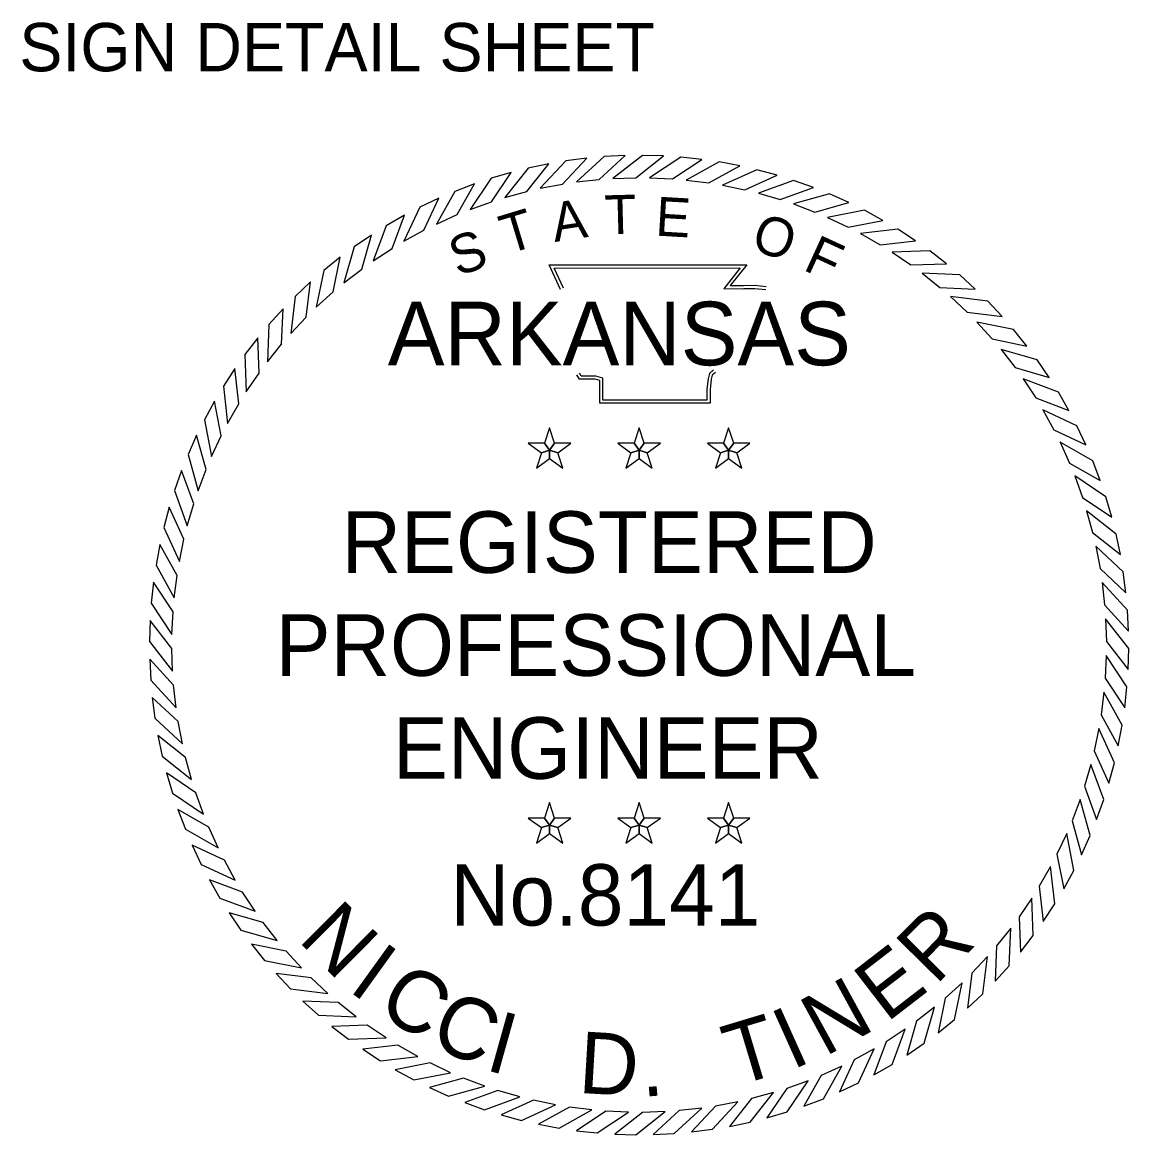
# Model space of a CAD drawing. Extents: x 1001970.7 to 1001981.7, y 1841148.9 to 1841208.3.
import ezdxf

# ---------------------------------------------------------------- set-up
doc = ezdxf.new("R2010")
doc.units = 0
doc.layers.add('G-ANNO-SYMB', color=7, linetype='Continuous')
doc.layers.add('G-ANNO-TEXT', color=7, linetype='Continuous')

msp = doc.modelspace()

# ---------------------------------------------------------------- linework, layer by layer
at = {"layer": 'G-ANNO-SYMB'}
for points in [[(1001977.6873, 1841207.3349), (1001977.5317, 1841207.3147), (1001977.3411, 1841207.1103), (1001977.5075, 1841207.1421)], [(1001977.973, 1841207.3543), (1001977.8164, 1841207.3464), (1001977.6103, 1841207.1575), (1001977.7787, 1841207.1762)], [(1001978.2594, 1841207.3512), (1001978.1026, 1841207.3557), (1001977.8823, 1841207.1836), (1001978.0517, 1841207.1889)], [(1001978.5447, 1841207.3257), (1001978.3887, 1841207.3424), (1001978.1556, 1841207.1881), (1001978.3249, 1841207.1802)], [(1001977.404, 1841207.2931), (1001977.2505, 1841207.2608), (1001977.0764, 1841207.042), (1001977.2399, 1841207.0868)], [(1001978.8271, 1841207.2779), (1001978.6729, 1841207.3068), (1001978.4284, 1841207.1713), (1001978.5965, 1841207.1501)], [(1001979.1048, 1841207.208), (1001978.9534, 1841207.249), (1001978.699, 1841207.133), (1001978.865, 1841207.0987)], [(1001977.1248, 1841207.2292), (1001976.9743, 1841207.185), (1001976.8179, 1841206.9532), (1001976.9774, 1841207.0107)], [(1001979.3763, 1841207.1166), (1001979.2285, 1841207.1693), (1001978.9658, 1841207.0737), (1001979.1286, 1841207.0265)], [(1001976.8515, 1841207.1436), (1001976.7049, 1841207.0877), (1001976.5672, 1841206.8444), (1001976.7217, 1841206.9142)], [(1001979.6397, 1841207.0042), (1001979.4965, 1841207.0683), (1001979.2271, 1841206.9936), (1001979.3857, 1841206.9338)], [(1001976.5857, 1841207.0368), (1001976.444, 1841206.9696), (1001976.3258, 1841206.7163), (1001976.4743, 1841206.7979)], [(1001976.3291, 1841206.9095), (1001976.1931, 1841206.8314), (1001976.0952, 1841206.5696), (1001976.2368, 1841206.6626)], [(1001979.8935, 1841206.8715), (1001979.7558, 1841206.9466), (1001979.4813, 1841206.8933), (1001979.6347, 1841206.8212)], [(1001976.0834, 1841206.7625), (1001975.9539, 1841206.674), (1001975.8768, 1841206.4052), (1001976.0107, 1841206.5091)], [(1001980.136, 1841206.7192), (1001980.0047, 1841206.8049), (1001979.7269, 1841206.7733), (1001979.8741, 1841206.6894)], [(1001975.8499, 1841206.5967), (1001975.7278, 1841206.4982), (1001975.672, 1841206.2243), (1001975.7973, 1841206.3384)], [(1001980.3659, 1841206.5484), (1001980.2417, 1841206.6442), (1001979.9623, 1841206.6344), (1001980.1025, 1841206.5392)], [(1001975.6301, 1841206.413), (1001975.5161, 1841206.3053), (1001975.482, 1841206.0278), (1001975.598, 1841206.1514)], [(1001980.5817, 1841206.3601), (1001980.4654, 1841206.4653), (1001980.1861, 1841206.4775), (1001980.3184, 1841206.3716)], [(1001980.7821, 1841206.1554), (1001980.6743, 1841206.2694), (1001980.3969, 1841206.3035), (1001980.5204, 1841206.1875)], [(1001975.4254, 1841206.2127), (1001975.3202, 1841206.0963), (1001975.308, 1841205.817), (1001975.4139, 1841205.9493)], [(1001980.9657, 1841205.9357), (1001980.8673, 1841206.0578), (1001980.5933, 1841206.1135), (1001980.7074, 1841205.9882)], [(1001975.2371, 1841205.9969), (1001975.1414, 1841205.8727), (1001975.1511, 1841205.5933), (1001975.2463, 1841205.7334)], [(1001981.1316, 1841205.7022), (1001981.043, 1841205.8316), (1001980.7743, 1841205.9087), (1001980.8782, 1841205.7748)], [(1001975.0663, 1841205.767), (1001974.9806, 1841205.6356), (1001975.0122, 1841205.3579), (1001975.0962, 1841205.5051)], [(1001981.2786, 1841205.4564), (1001981.2005, 1841205.5924), (1001980.9386, 1841205.6903), (1001981.0317, 1841205.5487)], [(1001974.9141, 1841205.5244), (1001974.8389, 1841205.3867), (1001974.8923, 1841205.1123), (1001974.9644, 1841205.2656)], [(1001981.4059, 1841205.1998), (1001981.3387, 1841205.3416), (1001981.0853, 1841205.4597), (1001981.167, 1841205.3112)], [(1001977.4103, 1841205.1607), (1001977.4478, 1841205.2122), (1001977.4103, 1841205.3274), (1001977.3729, 1841205.2122)], [(1001978.0773, 1841205.1607), (1001978.1147, 1841205.2122), (1001978.0773, 1841205.3274), (1001978.0399, 1841205.2122)], [(1001978.7443, 1841205.1607), (1001978.7817, 1841205.2122), (1001978.7443, 1841205.3274), (1001978.7068, 1841205.2122)], [(1001974.7813, 1841205.2706), (1001974.7172, 1841205.1275), (1001974.7919, 1841204.8581), (1001974.8518, 1841205.0166)], [(1001977.4103, 1841205.1607), (1001977.3729, 1841205.2122), (1001977.2517, 1841205.2122), (1001977.3497, 1841205.141)], [(1001977.4103, 1841205.1607), (1001977.3497, 1841205.141), (1001977.3123, 1841205.0258), (1001977.4103, 1841205.097)], [(1001977.4103, 1841205.1607), (1001977.4709, 1841205.141), (1001977.5689, 1841205.2122), (1001977.4478, 1841205.2122)], [(1001977.4103, 1841205.1607), (1001977.4103, 1841205.097), (1001977.5083, 1841205.0258), (1001977.4709, 1841205.141)], [(1001978.0773, 1841205.1607), (1001978.0399, 1841205.2122), (1001977.9187, 1841205.2122), (1001978.0167, 1841205.141)], [(1001978.0773, 1841205.1607), (1001978.0167, 1841205.141), (1001977.9793, 1841205.0258), (1001978.0773, 1841205.097)], [(1001978.0773, 1841205.1607), (1001978.1379, 1841205.141), (1001978.2359, 1841205.2122), (1001978.1147, 1841205.2122)], [(1001978.0773, 1841205.1607), (1001978.0773, 1841205.097), (1001978.1753, 1841205.0258), (1001978.1379, 1841205.141)], [(1001978.7443, 1841205.1607), (1001978.7068, 1841205.2122), (1001978.5857, 1841205.2122), (1001978.6837, 1841205.141)], [(1001978.7443, 1841205.1607), (1001978.6837, 1841205.141), (1001978.6463, 1841205.0258), (1001978.7443, 1841205.097)], [(1001978.7443, 1841205.1607), (1001978.8048, 1841205.141), (1001978.9029, 1841205.2122), (1001978.7817, 1841205.2122)], [(1001978.7443, 1841205.1607), (1001978.7443, 1841205.097), (1001978.8423, 1841205.0258), (1001978.8048, 1841205.141)], [(1001981.5127, 1841204.9341), (1001981.4568, 1841205.0806), (1001981.2135, 1841205.2183), (1001981.2832, 1841205.0639)], [(1001974.6689, 1841205.0072), (1001974.6162, 1841204.8595), (1001974.7118, 1841204.5968), (1001974.7591, 1841204.7595)], [(1001981.5982, 1841204.6608), (1001981.554, 1841204.8113), (1001981.3223, 1841204.9676), (1001981.3797, 1841204.8082)], [(1001974.5775, 1841204.7358), (1001974.5366, 1841204.5844), (1001974.6525, 1841204.33), (1001974.6868, 1841204.4959)], [(1001981.6621, 1841204.3816), (1001981.6299, 1841204.5351), (1001981.4111, 1841204.7091), (1001981.4558, 1841204.5457)], [(1001974.5077, 1841204.458), (1001974.4787, 1841204.3039), (1001974.6143, 1841204.0593), (1001974.6355, 1841204.2275)], [(1001981.7039, 1841204.0982), (1001981.6838, 1841204.2538), (1001981.4793, 1841204.4445), (1001981.5111, 1841204.278)], [(1001974.4598, 1841204.1756), (1001974.4431, 1841204.0197), (1001974.5974, 1841203.7866), (1001974.6053, 1841203.9558)], [(1001981.7233, 1841203.8125), (1001981.7155, 1841203.9691), (1001981.5266, 1841204.1753), (1001981.5452, 1841204.0068)], [(1001974.4343, 1841203.8904), (1001974.4299, 1841203.7336), (1001974.602, 1841203.5133), (1001974.5966, 1841203.6827)], [(1001981.7203, 1841203.5261), (1001981.7247, 1841203.6829), (1001981.5526, 1841203.9032), (1001981.558, 1841203.7338)], [(1001974.4313, 1841203.604), (1001974.4391, 1841203.4473), (1001974.628, 1841203.2412), (1001974.6093, 1841203.4096)], [(1001981.6947, 1841203.2408), (1001981.7115, 1841203.3968), (1001981.5572, 1841203.6299), (1001981.5493, 1841203.4607)], [(1001981.6469, 1841202.9585), (1001981.6759, 1841203.1126), (1001981.5403, 1841203.3571), (1001981.5191, 1841203.189)], [(1001974.4507, 1841203.3183), (1001974.4708, 1841203.1627), (1001974.6753, 1841202.972), (1001974.6435, 1841203.1385)], [(1001974.4925, 1841203.0349), (1001974.5247, 1841202.8814), (1001974.7435, 1841202.7074), (1001974.6988, 1841202.8708)], [(1001981.5771, 1841202.6807), (1001981.618, 1841202.8321), (1001981.5021, 1841203.0865), (1001981.4678, 1841202.9206)], [(1001974.5563, 1841202.7557), (1001974.6005, 1841202.6052), (1001974.8323, 1841202.4489), (1001974.7749, 1841202.6083)], [(1001981.4857, 1841202.4093), (1001981.5384, 1841202.557), (1001981.4428, 1841202.8197), (1001981.3955, 1841202.657)], [(1001977.4103, 1841202.3677), (1001977.4478, 1841202.4193), (1001977.4103, 1841202.5345), (1001977.3729, 1841202.4193)], [(1001978.0773, 1841202.3677), (1001978.1147, 1841202.4193), (1001978.0773, 1841202.5345), (1001978.0399, 1841202.4193)], [(1001978.7443, 1841202.3677), (1001978.7817, 1841202.4193), (1001978.7443, 1841202.5345), (1001978.7068, 1841202.4193)], [(1001981.3733, 1841202.1459), (1001981.4374, 1841202.289), (1001981.3627, 1841202.5584), (1001981.3028, 1841202.3999)], [(1001974.6419, 1841202.4824), (1001974.6978, 1841202.3358), (1001974.9411, 1841202.1982), (1001974.8714, 1841202.3526)], [(1001977.4103, 1841202.3677), (1001977.3729, 1841202.4193), (1001977.2517, 1841202.4193), (1001977.3497, 1841202.3481)], [(1001977.4103, 1841202.3677), (1001977.3497, 1841202.3481), (1001977.3123, 1841202.2328), (1001977.4103, 1841202.304)], [(1001977.4103, 1841202.3677), (1001977.4709, 1841202.3481), (1001977.5689, 1841202.4193), (1001977.4478, 1841202.4193)], [(1001977.4103, 1841202.3677), (1001977.4103, 1841202.304), (1001977.5083, 1841202.2328), (1001977.4709, 1841202.3481)], [(1001978.0773, 1841202.3677), (1001978.0399, 1841202.4193), (1001977.9187, 1841202.4193), (1001978.0167, 1841202.3481)], [(1001978.0773, 1841202.3677), (1001978.0167, 1841202.3481), (1001977.9793, 1841202.2328), (1001978.0773, 1841202.304)], [(1001978.0773, 1841202.3677), (1001978.1379, 1841202.3481), (1001978.2359, 1841202.4193), (1001978.1147, 1841202.4193)], [(1001978.0773, 1841202.3677), (1001978.0773, 1841202.304), (1001978.1753, 1841202.2328), (1001978.1379, 1841202.3481)], [(1001978.7443, 1841202.3677), (1001978.7068, 1841202.4193), (1001978.5857, 1841202.4193), (1001978.6837, 1841202.3481)], [(1001978.7443, 1841202.3677), (1001978.6837, 1841202.3481), (1001978.6463, 1841202.2328), (1001978.7443, 1841202.304)], [(1001978.7443, 1841202.3677), (1001978.8048, 1841202.3481), (1001978.9029, 1841202.4193), (1001978.7817, 1841202.4193)], [(1001978.7443, 1841202.3677), (1001978.7443, 1841202.304), (1001978.8423, 1841202.2328), (1001978.8048, 1841202.3481)], [(1001981.2405, 1841201.8921), (1001981.3157, 1841202.0298), (1001981.2623, 1841202.3042), (1001981.1902, 1841202.1508)], [(1001974.7487, 1841202.2167), (1001974.8159, 1841202.0749), (1001975.0693, 1841201.9568), (1001974.9876, 1841202.1053)], [(1001981.0883, 1841201.6495), (1001981.174, 1841201.7809), (1001981.1423, 1841202.0586), (1001981.0584, 1841201.9114)], [(1001974.876, 1841201.9601), (1001974.9541, 1841201.8241), (1001975.216, 1841201.7262), (1001975.1229, 1841201.8678)], [(1001980.9175, 1841201.4196), (1001981.0132, 1841201.5438), (1001981.0035, 1841201.8232), (1001980.9083, 1841201.683)], [(1001975.023, 1841201.7143), (1001975.1116, 1841201.5848), (1001975.3803, 1841201.5078), (1001975.2764, 1841201.6417)], [(1001980.7291, 1841201.2038), (1001980.8344, 1841201.3202), (1001980.8466, 1841201.5995), (1001980.7406, 1841201.4672)], [(1001975.1889, 1841201.4808), (1001975.2873, 1841201.3587), (1001975.5613, 1841201.303), (1001975.4472, 1841201.4283)], [(1001980.5245, 1841201.0035), (1001980.6385, 1841201.1112), (1001980.6726, 1841201.3887), (1001980.5566, 1841201.2651)], [(1001975.3725, 1841201.2611), (1001975.4802, 1841201.147), (1001975.7577, 1841201.113), (1001975.6342, 1841201.2289)], [(1001980.3047, 1841200.8198), (1001980.4268, 1841200.9183), (1001980.4826, 1841201.1922), (1001980.3573, 1841201.0781)], [(1001975.5729, 1841201.0564), (1001975.6892, 1841200.9512), (1001975.9685, 1841200.939), (1001975.8362, 1841201.0449)], [(1001980.0712, 1841200.654), (1001980.2007, 1841200.7425), (1001980.2778, 1841201.0112), (1001980.1439, 1841200.9073)], [(1001975.7887, 1841200.8681), (1001975.9129, 1841200.7723), (1001976.1923, 1841200.7821), (1001976.0521, 1841200.8773)], [(1001979.8254, 1841200.5069), (1001979.9615, 1841200.5851), (1001980.0594, 1841200.8469), (1001979.9178, 1841200.7538)], [(1001976.0185, 1841200.6973), (1001976.1499, 1841200.6115), (1001976.4277, 1841200.6432), (1001976.2805, 1841200.7271)], [(1001979.5689, 1841200.3796), (1001979.7106, 1841200.4468), (1001979.8288, 1841200.7002), (1001979.6803, 1841200.6185)], [(1001976.2611, 1841200.545), (1001976.3988, 1841200.4699), (1001976.6732, 1841200.5232), (1001976.5199, 1841200.5953)], [(1001979.3031, 1841200.2729), (1001979.4497, 1841200.3288), (1001979.5874, 1841200.5721), (1001979.4329, 1841200.5023)], [(1001976.5149, 1841200.4123), (1001976.6581, 1841200.3482), (1001976.9275, 1841200.4229), (1001976.7689, 1841200.4827)], [(1001979.0298, 1841200.1873), (1001979.1803, 1841200.2315), (1001979.3366, 1841200.4633), (1001979.1772, 1841200.4058)], [(1001976.7783, 1841200.2999), (1001976.9261, 1841200.2472), (1001977.1888, 1841200.3428), (1001977.026, 1841200.39)], [(1001978.7506, 1841200.1234), (1001978.9041, 1841200.1557), (1001979.0782, 1841200.3745), (1001978.9147, 1841200.3297)], [(1001977.0498, 1841200.2084), (1001977.2012, 1841200.1675), (1001977.4556, 1841200.2834), (1001977.2896, 1841200.3178)], [(1001978.4673, 1841200.0816), (1001978.6228, 1841200.1018), (1001978.8135, 1841200.3062), (1001978.6471, 1841200.2744)], [(1001977.3275, 1841200.1386), (1001977.4817, 1841200.1097), (1001977.7262, 1841200.2452), (1001977.5581, 1841200.2664)], [(1001977.6099, 1841200.0908), (1001977.7658, 1841200.074), (1001977.999, 1841200.2283), (1001977.8297, 1841200.2363)], [(1001977.8952, 1841200.0653), (1001978.0519, 1841200.0608), (1001978.2722, 1841200.2329), (1001978.1029, 1841200.2276)], [(1001978.1815, 1841200.0622), (1001978.3382, 1841200.0701), (1001978.5443, 1841200.2589), (1001978.3759, 1841200.2403)]]:
    msp.add_lwpolyline(points, close=True, dxfattribs=at)
for points in [[(1001977.4929, 1841206.3556), (1001977.4079, 1841206.5397), (1001978.8791, 1841206.5406), (1001978.7562, 1841206.3861), (1001978.8561, 1841206.3874), (1001978.9397, 1841206.3885), (1001979.0231, 1841206.3794)], [(1001977.5141, 1841206.3653), (1001977.4443, 1841206.5164), (1001978.8308, 1841206.5172), (1001978.7074, 1841206.3622), (1001978.8564, 1841206.3641), (1001978.9385, 1841206.3652), (1001979.0205, 1841206.3562)], [(1001978.6473, 1841205.739), (1001978.6222, 1841205.7186), (1001978.6139, 1841205.6881), (1001978.6056, 1841205.6118), (1001978.6056, 1841205.5101), (1001977.7843, 1841205.5101), (1001977.7843, 1841205.6474), (1001977.7843, 1841205.6779), (1001977.751, 1841205.6881), (1001977.6341, 1841205.6881), (1001977.6134, 1841205.7198)], [(1001978.6326, 1841205.7571), (1001978.6017, 1841205.7319), (1001978.5909, 1841205.6924), (1001978.5823, 1841205.6131), (1001978.5823, 1841205.5334), (1001977.8076, 1841205.5334), (1001977.8076, 1841205.6474), (1001977.8076, 1841205.6952), (1001977.7544, 1841205.7114), (1001977.6467, 1841205.7114), (1001977.6329, 1841205.7325)]]:
    msp.add_lwpolyline(points, dxfattribs=at)

# ---------------------------------------------------------------- texts
for s, height, rotation, p in [('A', 0.2902, 8.67877, (1001977.4481, 1841206.7097)), ('T', 0.2902, 1.47887, (1001977.8229, 1841206.7675)), ('E', 0.2902, 356.67203, (1001978.1943, 1841206.7587)), ('T', 0.2902, 16.90148, (1001977.0957, 1841206.6177)), ('O', 0.2902, 341.2218, (1001978.8989, 1841206.6591)), ('S', 0.2902, 19.77256, (1001976.7267, 1841206.4521)), ('F', 0.2902, 335.36282, (1001979.2901, 1841206.5062)), ('N', 0.4585, 315.26758, (1001975.5291, 1841201.5084)), ('R', 0.4585, 45.47796, (1001980.2865, 1841201.1681)), ('I', 0.4585, 324.21406, (1001975.9022, 1841201.1389)), ('E', 0.4585, 37.64979, (1001979.9199, 1841200.8909)), ('C', 0.4585, 328.68731, (1001976.1092, 1841200.9771)), ('N', 0.4585, 28.7033, (1001979.4593, 1841200.6386)), ('C', 0.4585, 336.51548, (1001976.4995, 1841200.7345)), ('I', 0.4585, 344.34365, (1001976.9193, 1841200.5473)), ('T', 0.4585, 16.77466, (1001978.795, 1841200.4193)), ('I', 0.4585, 24.23006, (1001979.2157, 1841200.5402)), ('D', 0.4585, 356.64507, (1001977.6193, 1841200.3732)), ('.', 0.4585, 4.84601, (1001978.0997, 1841200.3419))]:
    msp.add_text(s, height=height, rotation=rotation, dxfattribs=at).set_placement(p)
for s, height, p in [('ARKANSAS', 0.47365, (1001976.2052, 1841205.7919)), ('REGISTERED', 0.45855, (1001975.861, 1841204.2458)), ('PROFESSIONAL', 0.458545, (1001975.3697, 1841203.479)), ('ENGINEER', 0.45855, (1001976.2431, 1841202.7121)), ('No.8141', 0.45674, (1001976.6706, 1841201.619))]:
    msp.add_text(s, height=height, dxfattribs=at).set_placement(p)
at = {"layer": 'G-ANNO-TEXT'}
msp.add_text('SIGN DETAIL SHEET', height=0.36, dxfattribs=at).set_placement((1001973.4602, 1841207.9818))

doc.saveas('drawing.dxf')
